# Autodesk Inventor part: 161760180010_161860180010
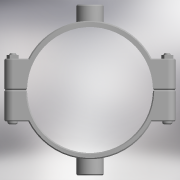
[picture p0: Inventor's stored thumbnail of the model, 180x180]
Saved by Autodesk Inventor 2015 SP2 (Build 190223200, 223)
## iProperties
Created: 2017-05
Part Number: 161760180010_161860180010
Material: Generic
Description: PLASSON DOUBLE SADDLE 180-1"
Document SubType Name: Modeling
Designer: KIM
Density: 1 g/cm^3
Appearance: Default
Author: KIM
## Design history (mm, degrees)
derived "16176.ipt"
feature "Solid1::16176.ipt"
feature "Solid2::16176.ipt"
tag "TaggingFeature1"
body "Solid1"
body "Solid2"
other parameters: "d0" = 198, "d1" = 245, "d4" = 154, "d5" = 0, "d6" = 12.25, "d7" = 245, "d8" = 0.1, "d10" = 0, "d11" = 1.8, "d20" = 1.8, "d23" = 1.8, "d36" = 15, "d37" = 12, "d38" = 98, "d39" = 0, "d40" = 3, "d41" = 5, "d42" = 0, "d44" = 3, "d45" = 0, "d46" = 1.8, "d52" = 30.291, "d53" = 21, "d54" = 0, "d55" = 25, "d57" = 0, "d58" = 194.4, "d60" = 0, "d62" = 15, "d63" = 12, "d67" = 244, "d68" = 39.3783, "d69" = 30.291, "d70" = 21, "d71" = 0, "d72" = 25, "d74" = 0, "d75" = 1.8, "B_" = 25, "G_" = 30.291, "A_" = 122, "L_" = 245, "L_1" = 154, "l_2" = 21
